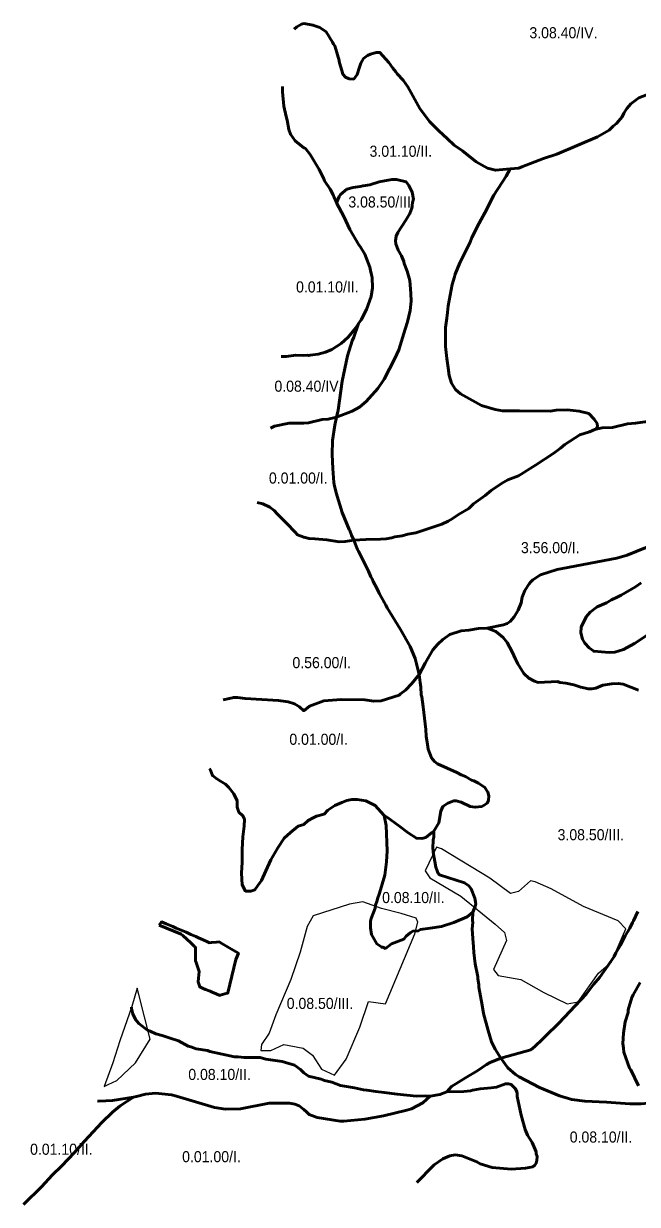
# Model space of a CAD drawing. Extents: x -555506 to -553028, y -1186750 to -1182668.
# Drawn here: x -555506 to -554397, y -1186706 to -1184575 of the extents above; entities that cross this region are included whole.
import ezdxf
from ezdxf.enums import TextEntityAlignment as Align

# ---------------------------------------------------------------- set-up
doc = ezdxf.new("R2010")
doc.units = 0
doc.header["$LTSCALE"] = 8
doc.layers.add('21', color=7, linetype='Continuous', lineweight=53)
doc.layers.add('41', color=7, linetype='Continuous', lineweight=25)
doc.layers.add('22', color=7, linetype='Continuous')

msp = doc.modelspace()

# ---------------------------------------------------------------- linework, layer by layer
at = {"layer": '21'}
for points in [[(-555017.062, -1184585.205), (-555012.312, -1184581.125), (-555003.812, -1184576), (-555000, -1184575.126), (-554989.375, -1184576.875), (-554983.437, -1184577.625), (-554971.125, -1184582.375), (-554959.25, -1184590.001), (-554947.812, -1184608.626), (-554946.125, -1184612), (-554944, -1184615.376), (-554940.187, -1184627.25), (-554938.062, -1184635.75), (-554936.812, -1184639.125), (-554935.5, -1184646.001), (-554931.25, -1184659.5), (-554929.125, -1184666.251), (-554924.5, -1184671.75), (-554917.687, -1184674.751), (-554909.625, -1184675.251), (-554903.312, -1184667.125), (-554899.5, -1184653.625), (-554897.75, -1184650.125), (-554896.937, -1184646.751), (-554892.25, -1184638.251), (-554885.062, -1184632.75), (-554879.562, -1184630.251), (-554868.937, -1184627.25), (-554862.562, -1184627.25), (-554846.5, -1184645.126), (-554839.25, -1184655.251), (-554833.312, -1184662.001), (-554831.187, -1184665.5), (-554820.625, -1184677.376), (-554811.687, -1184689.126), (-554790.5, -1184728.251), (-554772.687, -1184751.875), (-554756.187, -1184768.876), (-554740.937, -1184782.5), (-554728.187, -1184794.376), (-554713.375, -1184804.501), (-554688.75, -1184824.875), (-554668, -1184835.875), (-554653.562, -1184839.751), (-554626.875, -1184837.125)], [(-555038.125, -1184688.404), (-555038.125, -1184695.125), (-555038.562, -1184698.501), (-555036, -1184723.875), (-555031.75, -1184742.5), (-555030.062, -1184749.25), (-555026.687, -1184766.25), (-555024.125, -1184774.75), (-555015.687, -1184786.626), (-555000, -1184799.126), (-554997, -1184800.625), (-554988.062, -1184811.25), (-554972.375, -1184838.376), (-554963.5, -1184855.376), (-554962.25, -1184858.75), (-554952.5, -1184874.001), (-554946.937, -1184884.251), (-554944.875, -1184889.251), (-554943.125, -1184892.751), (-554940.625, -1184898.626)], [(-554626.875, -1184837.125), (-554611.625, -1184835.875), (-554606.062, -1184833.375), (-554566.625, -1184818.5), (-554542.5, -1184810.5), (-554469.562, -1184779.501), (-554447.937, -1184767.251), (-554440.75, -1184760.375), (-554435.25, -1184755.375), (-554424.625, -1184743.501), (-554421.625, -1184736.626), (-554416.125, -1184728.251), (-554408.937, -1184719.751), (-554394.5, -1184709.126), (-554378.812, -1184703.125), (-554375, -1184701), (-554364, -1184690.875)], [(-554940.625, -1184898.626), (-554935.937, -1184887.126), (-554933.375, -1184883.75), (-554921.937, -1184874.001), (-554910.937, -1184871.126), (-554898.187, -1184869.375), (-554892.687, -1184867.626), (-554880.812, -1184866), (-554863.437, -1184860.875), (-554840.562, -1184856.251), (-554832.5, -1184856.251), (-554814.687, -1184860.875), (-554810, -1184867.25), (-554804.062, -1184879.126), (-554801.937, -1184892.25), (-554803.25, -1184897.751), (-554804.937, -1184908), (-554808.312, -1184918.125), (-554815.5, -1184930.001), (-554829.937, -1184952), (-554832.937, -1184958.875), (-554834.187, -1184967.376), (-554833.75, -1184972.376), (-554829.125, -1184984.25), (-554823.562, -1184994.501), (-554819.375, -1185004.626), (-554818.5, -1185008), (-554813, -1185021.626), (-554808.312, -1185038.501), (-554806.625, -1185062.25), (-554805.75, -1185075.875), (-554807.875, -1185092.75), (-554812.562, -1185113.126), (-554816.812, -1185126.75), (-554828.25, -1185164.001), (-554835.437, -1185179.25), (-554854.562, -1185216.625), (-554866, -1185233.625), (-554887.187, -1185257.375), (-554899.5, -1185267.5), (-554912.625, -1185274.751), (-554940.625, -1185285.251)], [(-554626.875, -1184837.125), (-554634.5, -1184850.75), (-554656.562, -1184884.625), (-554662.062, -1184894.876), (-554669.25, -1184910.125), (-554683.25, -1184935.5), (-554696.375, -1184961), (-554699.375, -1184969.375), (-554707.812, -1184986.375), (-554718, -1185006.751), (-554726.5, -1185027.125), (-554727.75, -1185032.126), (-554732, -1185045.75), (-554737.125, -1185074.625), (-554738.812, -1185084.75), (-554740.062, -1185096.625), (-554741.75, -1185106.75), (-554743.875, -1185123.751), (-554743.875, -1185157.626), (-554741.312, -1185179.75), (-554739.187, -1185196.625), (-554737.125, -1185210.25), (-554732.875, -1185223.876), (-554726.062, -1185235.75), (-554716.75, -1185243.376), (-554679, -1185264.126), (-554654, -1185271.75), (-554640.875, -1185274.251), (-554610.312, -1185273.875), (-554554.812, -1185274.751), (-554544.187, -1185273.001), (-554524.25, -1185272.126), (-554502.187, -1185274.751), (-554485.25, -1185279), (-554475.5, -1185288.75), (-554470, -1185297.126), (-554469.562, -1185302.251), (-554471.687, -1185306.875)], [(-554940.625, -1184898.626), (-554927.437, -1184923.25), (-554916.875, -1184947), (-554900.312, -1184974.125), (-554897.75, -1184977.501), (-554889.75, -1184991.001), (-554880.375, -1185014.751), (-554879.125, -1185020.75), (-554877.437, -1185028.376), (-554876.562, -1185033.5), (-554875.75, -1185052.125), (-554878.25, -1185067.375), (-554886.75, -1185091.125), (-554896.062, -1185109.75), (-554900.75, -1185116.501)], [(-555040.994, -1185176.151), (-555031.75, -1185175.626), (-555014, -1185173.501), (-555000, -1185174), (-554993.625, -1185173.75), (-554990.625, -1185174.25), (-554988.062, -1185173.375), (-554974.125, -1185171.626), (-554960.937, -1185168.251), (-554949.062, -1185163.25), (-554932.562, -1185152.625), (-554919.812, -1185140.751), (-554905.812, -1185124.125), (-554900.75, -1185116.501)], [(-554900.75, -1185116.501), (-554909.25, -1185140.751), (-554912.625, -1185147.501), (-554920.687, -1185174.626), (-554930.437, -1185220.375), (-554938.062, -1185273.001), (-554940.625, -1185285.251)], [(-554940.625, -1185285.251), (-554955.875, -1185289.126), (-554966.437, -1185289.501), (-554991.062, -1185295.5), (-555000, -1185296.376), (-555026.25, -1185296.376), (-555052.562, -1185301.501), (-555059.967, -1185305.013)], [(-554940.625, -1185285.251), (-554943.562, -1185300.126), (-554948.25, -1185327.251), (-554948.687, -1185352.75), (-554947.375, -1185378.126), (-554945.687, -1185403.625), (-554944.875, -1185407.001), (-554941.437, -1185422.25), (-554930.437, -1185457.376), (-554917.687, -1185488.375), (-554916.437, -1185490.126), (-554913.5, -1185498.5), (-554909.625, -1185507.5)], [(-554246.562, -1185309.875), (-554256.312, -1185301), (-554273.25, -1185293.375), (-554280.062, -1185291.25), (-554313.125, -1185287.001), (-554342.375, -1185289.126), (-554354.687, -1185290.751), (-554375, -1185292.5), (-554400.875, -1185296.376), (-554415.312, -1185297.625), (-554442, -1185304), (-554461.062, -1185304.75), (-554471.687, -1185306.875)], [(-554909.625, -1185507.5), (-554888, -1185506.25), (-554861.312, -1185505.75), (-554851.125, -1185504.875), (-554841, -1185503.25), (-554835.437, -1185501.501), (-554822.312, -1185499.875), (-554812.125, -1185496.875), (-554797.312, -1185493.876), (-554750.687, -1185478.626), (-554739.187, -1185473.125), (-554732, -1185468.875), (-554720.562, -1185461.25), (-554701.5, -1185450.25), (-554693.437, -1185441.75), (-554672.25, -1185426.5), (-554661.187, -1185418), (-554642.562, -1185405.25), (-554631.125, -1185398.501), (-554612, -1185391.251), (-554581.5, -1185372.25), (-554548.437, -1185350.125), (-554536.125, -1185341.626), (-554528.062, -1185334.875), (-554501.375, -1185317.126), (-554484, -1185311.626), (-554474.25, -1185307.376), (-554471.687, -1185306.875)], [(-555083.848, -1185439.632), (-555074.125, -1185442.126), (-555061, -1185448.001), (-555053.375, -1185454), (-555047.062, -1185460.751), (-555041.937, -1185465.876), (-555037.312, -1185471), (-555030.5, -1185477.251), (-555015.25, -1185493.001), (-555011, -1185497.625), (-555000, -1185502.25), (-554990.187, -1185504.501), (-554979.625, -1185504.875), (-554958.437, -1185507), (-554935.937, -1185510.376), (-554924.937, -1185510), (-554909.625, -1185507.5)], [(-554668.812, -1185666.001), (-554639.125, -1185660.5), (-554632.375, -1185658.001), (-554627.312, -1185654.125), (-554620.062, -1185645.625), (-554612.437, -1185633.751), (-554606.937, -1185620.25), (-554605.25, -1185610.001), (-554600.562, -1185598.251), (-554592.937, -1185586.375), (-554589.562, -1185582.876), (-554586.187, -1185579.126), (-554572.187, -1185570.251), (-554542.062, -1185560.501), (-554532.312, -1185558.75), (-554434.375, -1185539.626), (-554415.75, -1185534.626), (-554383.062, -1185521.001), (-554358.875, -1185506.626), (-554332.187, -1185482.876)], [(-554909.625, -1185507.5), (-554902.875, -1185524.375), (-554901.187, -1185527.376), (-554882.937, -1185563.376), (-554878.687, -1185573.625), (-554876.562, -1185577.001), (-554874.437, -1185582.125), (-554868.125, -1185594.001), (-554865.125, -1185600.75), (-554863, -1185604.126), (-554854.937, -1185619.376), (-554851.562, -1185624.5), (-554849, -1185629.625), (-554825.25, -1185668.626), (-554807.5, -1185699.125), (-554798.562, -1185721.126), (-554791.375, -1185750)], [(-554390.687, -1185584.626), (-554400.437, -1185591.376), (-554426.312, -1185606.625), (-554433.937, -1185610.001), (-554444.125, -1185615.126), (-554453, -1185620.626), (-554470, -1185627.876), (-554482.687, -1185637.25), (-554489.937, -1185645.625), (-554498.812, -1185664.376), (-554499.25, -1185674.501), (-554496.25, -1185686.375), (-554492.062, -1185693.126), (-554484.375, -1185701.626), (-554475.937, -1185708.001), (-554448.375, -1185710.126), (-554437.75, -1185709.25), (-554422.062, -1185704.626), (-554402.562, -1185694), (-554374.187, -1185675.375)], [(-554791.375, -1185750), (-554780.75, -1185729.25), (-554766.75, -1185705.5), (-554757.437, -1185695.251), (-554748.937, -1185686.751), (-554736.25, -1185677.5), (-554715.5, -1185671.125), (-554701.5, -1185669.875), (-554684.125, -1185666.875), (-554668.812, -1185666.001)], [(-554395.375, -1185778.376), (-554422.937, -1185767.375), (-554432.25, -1185766.126), (-554443.25, -1185766.5), (-554459.812, -1185769), (-554472.562, -1185774.626), (-554479.312, -1185775.875), (-554485.687, -1185775.875), (-554499.687, -1185772.875), (-554511.937, -1185768.625), (-554526.812, -1185765.25), (-554537.375, -1185764.001), (-554541.625, -1185762.75), (-554576.437, -1185764.001), (-554583.187, -1185761.876), (-554593.375, -1185756.375), (-554602.25, -1185747.875), (-554613.312, -1185730.875), (-554617.562, -1185722.376), (-554623.5, -1185708.876), (-554632.375, -1185691.875), (-554639.562, -1185683.375), (-554652.75, -1185672), (-554668.812, -1185666.001)], [(-555145.556, -1185795.729), (-555134.312, -1185793.001), (-555126.25, -1185791.251), (-555119.5, -1185791.251), (-555105.937, -1185793.001), (-555045.75, -1185796.751), (-555028.375, -1185799.375), (-555016.5, -1185802.75), (-555007.625, -1185808.251), (-555000, -1185815.25), (-554989.812, -1185807.25), (-554963.937, -1185797.5), (-554932.562, -1185794.876), (-554889.75, -1185795.375), (-554873.625, -1185798.25), (-554860.062, -1185797.5), (-554827.812, -1185786.876), (-554824.875, -1185784.751), (-554815.937, -1185778), (-554804.5, -1185766.126), (-554791.375, -1185750)], [(-554791.375, -1185750), (-554789.687, -1185764.375), (-554788.375, -1185772.875), (-554787.562, -1185786.5), (-554786.687, -1185789.876), (-554784.125, -1185808.501), (-554779.5, -1185849.125), (-554778.625, -1185861.001), (-554776.5, -1185876.375), (-554775.25, -1185884.751), (-554768.875, -1185900.126), (-554763.812, -1185906.876), (-554758.312, -1185911.126), (-554723.125, -1185926.75), (-554715.875, -1185931), (-554707.812, -1185934.001), (-554696.812, -1185940.376), (-554692.562, -1185941.625), (-554690.062, -1185943.25), (-554684.125, -1185945.875), (-554672.625, -1185953.501), (-554667.125, -1185962.001), (-554665.437, -1185968.75), (-554666.312, -1185977.25), (-554668.812, -1185982.375), (-554673.937, -1185985.751), (-554678.187, -1185987.876), (-554690.062, -1185989.5), (-554699.375, -1185988.25), (-554715.5, -1185980.25), (-554724.812, -1185978.125), (-554729.062, -1185978.125), (-554739.625, -1185981.875), (-554748.562, -1185988.25), (-554752.375, -1185996.75), (-554755.75, -1186017.5), (-554765.062, -1186032.75)], [(-554854.937, -1186004.376), (-554860.875, -1185997.626), (-554871.062, -1185986.125), (-554887.625, -1185978.125), (-554903.312, -1185975.5), (-554913.062, -1185975.5), (-554921.937, -1185977.25), (-554931.25, -1185980.626), (-554943.562, -1185986.125), (-554956.687, -1185995.001), (-554963.062, -1186001.875), (-554976.625, -1186005.626), (-554983, -1186008.626), (-554991.875, -1186013.25), (-555000, -1186020.626), (-555009.75, -1186023.501), (-555023.75, -1186035.001), (-555035.187, -1186045.5), (-555046.625, -1186062.875), (-555059.312, -1186084.501), (-555068.25, -1186104.001), (-555076.25, -1186121.376), (-555083.062, -1186130.75), (-555088.562, -1186138.376), (-555095.75, -1186140.875), (-555105.062, -1186140.875), (-555111.437, -1186129.376), (-555112.687, -1186108.625), (-555111, -1186088.75), (-555111, -1186076.001), (-555111, -1186065.876), (-555110.187, -1186042.625), (-555107.625, -1186023.501), (-555107.187, -1186011.251), (-555110.187, -1186004.876), (-555117.375, -1185998.125), (-555120.375, -1185989.126), (-555120.375, -1185977.751), (-555126.25, -1185965), (-555135.187, -1185954.001), (-555141.5, -1185947.626), (-555150.437, -1185942.501), (-555157.187, -1185938.375), (-555164.812, -1185932.376), (-555168.625, -1185922.251), (-555169.98, -1185919.441)], [(-554694.25, -1186178.626), (-554704.875, -1186187.5), (-554728.625, -1186197.251), (-554751.062, -1186204.501), (-554771.875, -1186207.5), (-554788.812, -1186210.376), (-554793.5, -1186212.501), (-554802.812, -1186213.375), (-554807.875, -1186215.876), (-554814.687, -1186221.875), (-554819.375, -1186227.75), (-554841.375, -1186236.25), (-554852.437, -1186244.376), (-554857.062, -1186242.251), (-554859.187, -1186242.251), (-554867.687, -1186235.876), (-554877.437, -1186218.876), (-554879.125, -1186207), (-554879.562, -1186195.126), (-554877.875, -1186190.126), (-554871.062, -1186171.376), (-554870.25, -1186166.376), (-554867.25, -1186157.876), (-554866.812, -1186154.5), (-554863, -1186144.251), (-554853.687, -1186112.001), (-554850.312, -1186088.251), (-554849, -1186068.001), (-554851.125, -1186022.125), (-554854.937, -1186004.376)], [(-554765.062, -1186032.75), (-554769.312, -1186035.751), (-554779.5, -1186044.25), (-554786.687, -1186045.876), (-554796.437, -1186045.5), (-554811.312, -1186035.751), (-554828.687, -1186022.125), (-554848.625, -1186007.75), (-554854.937, -1186004.376)], [(-554694.25, -1186178.626), (-554690.437, -1186168.875), (-554689.187, -1186163.751), (-554690.875, -1186153.626), (-554697.687, -1186136.625), (-554701.5, -1186131.501), (-554709.562, -1186125.626), (-554754.875, -1186111.251), (-554757.437, -1186107.751), (-554759.125, -1186104.375), (-554761.25, -1186097.626), (-554766.375, -1186070.5), (-554766.375, -1186067.125), (-554766.75, -1186063.751), (-554766.375, -1186048.5), (-554765.062, -1186043.375), (-554765.062, -1186032.75)], [(-554643.812, -1186442.376), (-554654.437, -1186426.25), (-554658.25, -1186417.75), (-554660.75, -1186412.625), (-554666.687, -1186392.251), (-554675.187, -1186361.75), (-554677.75, -1186346.501), (-554683.687, -1186314.251), (-554683.687, -1186309.25), (-554685.375, -1186299.001), (-554685.375, -1186295.626), (-554686.187, -1186292.25), (-554690.437, -1186271.876), (-554693, -1186251.5), (-554693.437, -1186241.375), (-554694.687, -1186226.125), (-554696, -1186209.125), (-554694.687, -1186197.251), (-554695.125, -1186193.875), (-554694.25, -1186178.626)], [(-554643.812, -1186442.376), (-554590, -1186427.125), (-554582.375, -1186421.5), (-554568.75, -1186408.001), (-554563.25, -1186402.875), (-554539.125, -1186379.125), (-554489.937, -1186326.625), (-554476.375, -1186309.625), (-554464.875, -1186296), (-554457.687, -1186285.875), (-554450.5, -1186275.75), (-554439.062, -1186258.751), (-554436.062, -1186252), (-554428, -1186238.375), (-554419.562, -1186221.501), (-554410.625, -1186207.876), (-554406, -1186197.751), (-554404.25, -1186194.25), (-554396.187, -1186177.375)], [(-554395.375, -1186492.375), (-554409.375, -1186463.501), (-554411.5, -1186460.125), (-554421.625, -1186431.251), (-554422.5, -1186424.501), (-554423.75, -1186416.001), (-554422.062, -1186397.376), (-554419.125, -1186377), (-554414, -1186360.126), (-554413.625, -1186355.001), (-554407.25, -1186333), (-554404.687, -1186327.876), (-554392.375, -1186305.751)], [(-554771.437, -1186511), (-554779.5, -1186510.126), (-554796.437, -1186510.626), (-554831.187, -1186507.25), (-554854.562, -1186504.251), (-554869.812, -1186502.5), (-554885.937, -1186500.001), (-554891.875, -1186499.626), (-554908.375, -1186495.751), (-554933.812, -1186491.875), (-554949.062, -1186485.626), (-554962.625, -1186482.626), (-554968.187, -1186480.501), (-554991.062, -1186475), (-555000, -1186468.751), (-555005.937, -1186462.5), (-555016.5, -1186454.876), (-555039, -1186448.501), (-555068.625, -1186443.875), (-555078.375, -1186440.875), (-555107.625, -1186441.25), (-555118.25, -1186440.001), (-555125, -1186440.001), (-555147.437, -1186435.001), (-555169.5, -1186430.25), (-555173.75, -1186428.625), (-555194.062, -1186425.25), (-555203.812, -1186421.876), (-555208.5, -1186420.501), (-555226.25, -1186411.251), (-555241.125, -1186406.5), (-555255.5, -1186401.5), (-555267.375, -1186398.126), (-555277.562, -1186393.376), (-555282.187, -1186391.751), (-555286.875, -1186387.875), (-555297.875, -1186379.501), (-555303.812, -1186372.626), (-555308.5, -1186362.501), (-555311, -1186352.376), (-555311.091, -1186350.268)], [(-554741.75, -1186503), (-554733.25, -1186493.625), (-554707.812, -1186477.5), (-554685.375, -1186464.751), (-554669.687, -1186453.75), (-554663.312, -1186450.376), (-554643.812, -1186442.376)], [(-554643.812, -1186442.376), (-554631.5, -1186459.751), (-554617.562, -1186471.625), (-554610.75, -1186475.875), (-554573.875, -1186495.376), (-554538.25, -1186510.126), (-554515.75, -1186517.001), (-554492.062, -1186519.876), (-554453, -1186521.625), (-554411.062, -1186524.625), (-554390.25, -1186524.625), (-554377.562, -1186523.75), (-554366.937, -1186524.625)], [(-554741.75, -1186503), (-554710.812, -1186502.5), (-554698.5, -1186501.251), (-554694.687, -1186500.001), (-554681.562, -1186497.501), (-554661.187, -1186495.751), (-554651.875, -1186494.5), (-554635.312, -1186488.501), (-554629.812, -1186488.501), (-554625.187, -1186489.876), (-554617.562, -1186497.876), (-554615, -1186503), (-554614.125, -1186506.376), (-554614.125, -1186511.5), (-554606.937, -1186545.375), (-554600.125, -1186570.75), (-554595.5, -1186581.001), (-554587.437, -1186594.501), (-554580.25, -1186611.5), (-554580.25, -1186614.875), (-554578.5, -1186620), (-554578.937, -1186626.751), (-554580.25, -1186631.876), (-554582.75, -1186635.251), (-554586.187, -1186638.251), (-554599.312, -1186641.126), (-554625.562, -1186642.501), (-554659.5, -1186639.5), (-554681.125, -1186632.75), (-554687.062, -1186629.25), (-554714.625, -1186618.751), (-554726.5, -1186617), (-554736.25, -1186618.751), (-554748.937, -1186624.25), (-554764.25, -1186634.875), (-554774.375, -1186645), (-554787.125, -1186658.501), (-554795.617, -1186666.413)], [(-555307.625, -1186512.875), (-555331.375, -1186528.126), (-555345.375, -1186540), (-555364.812, -1186558.626), (-555395.75, -1186592.126), (-555405.5, -1186602.751), (-555414.437, -1186612.876), (-555436.875, -1186636.626), (-555454.25, -1186653.626), (-555473.312, -1186674.001), (-555506.016, -1186706.203)], [(-555372.298, -1186519.611), (-555369.5, -1186519.75), (-555345.375, -1186518.876), (-555307.625, -1186512.875)], [(-555307.625, -1186512.875), (-555302.125, -1186511.25), (-555286, -1186507.376), (-555267.812, -1186505.75), (-555239, -1186508.625), (-555229.687, -1186510.75), (-555161, -1186531.626), (-555141.125, -1186534.5), (-555114, -1186533.625), (-555062.687, -1186523.5), (-555025.437, -1186523.5), (-555016.125, -1186525.251), (-555008.062, -1186528.625), (-555000, -1186534.75), (-554994.875, -1186539.376), (-554990.187, -1186544.126), (-554975.812, -1186549.125), (-554934.25, -1186556), (-554927.437, -1186556), (-554889.312, -1186552.126), (-554855.812, -1186546.25), (-554813.812, -1186536), (-554805.375, -1186533.501), (-554785, -1186522.876), (-554771.437, -1186511)], [(-554771.437, -1186511), (-554754.062, -1186508.001), (-554741.75, -1186503)]]:
    msp.add_lwpolyline(points, dxfattribs=at)
msp.add_lwpolyline([(-555261.28, -1186202.32), (-555256.91, -1186196.5), (-555248.77, -1186199.76), (-555242.74, -1186202.33), (-555236.71, -1186204.91), (-555230.2, -1186207.64), (-555212.56, -1186215.1), (-555203.72, -1186218.85), (-555194.89, -1186222.61), (-555190.05, -1186224.85), (-555185.99, -1186226.72), (-555175.06, -1186231.77), (-555170.16, -1186234.03), (-555166.5, -1186233.72), (-555157.32, -1186232.94), (-555153.01, -1186232.57), (-555147.8, -1186235.58), (-555137.45, -1186241.58), (-555127.54, -1186247.31), (-555121.87, -1186250.59), (-555117.88, -1186252.9), (-555122.79, -1186264.03), (-555136.85, -1186324.41), (-555138.36, -1186325.06), (-555142.52, -1186326.28), (-555150.68, -1186328.68), (-555151.71, -1186328.98), (-555157.95, -1186326.36), (-555165.36, -1186323.24), (-555169.27, -1186321.6), (-555177.22, -1186318.25), (-555181.71, -1186316.36), (-555186.26, -1186314.45), (-555187.71, -1186313.84), (-555190.76, -1186304.59), (-555190.1, -1186297.86), (-555188.93, -1186285.88), (-555194.7, -1186268.11), (-555195.22, -1186267.63), (-555195.64, -1186245.84), (-555195.72, -1186241.89), (-555197.18, -1186240.55), (-555204.2, -1186234.11), (-555218.31, -1186221.15), (-555221.4, -1186218.64)], close=True, dxfattribs=at)
at = {"layer": '41'}
for points in [[(-554760.17, -1186061.511), (-554780.396, -1186104.412), (-554772.306, -1186116.554), (-554716.481, -1186149.742), (-554654.183, -1186200.738), (-554637.192, -1186215.308), (-554633.956, -1186229.879), (-554657.419, -1186282.494), (-554648.519, -1186293.017), (-554608.066, -1186300.302)], [(-554608.066, -1186300.302), (-554565.995, -1186323.776), (-554523.924, -1186344.013), (-554504.506, -1186340.775), (-554467.289, -1186288.97), (-554443.827, -1186268.733), (-554417.937, -1186208.833), (-554431.691, -1186194.262), (-554494.798, -1186168.36), (-554553.05, -1186136.791), (-554582.176, -1186123.839), (-554590.267, -1186122.22), (-554612.112, -1186141.647), (-554626.675, -1186144.885), (-554663.891, -1186117.364), (-554751.27, -1186064.748), (-554760.17, -1186061.511)], [(-555059.12, -1186428.197), (-555035.657, -1186417.674), (-555000.868, -1186424.15), (-554983.878, -1186437.101), (-554967.696, -1186462.195), (-554944.233, -1186472.718), (-554923.198, -1186444.386), (-554898.926, -1186386.105), (-554882.745, -1186339.966), (-554852, -1186344.013), (-554799.411, -1186217.737), (-554793.748, -1186196.691), (-554796.984, -1186189.406), (-554823.683, -1186181.311), (-554859.282, -1186172.407), (-554893.263, -1186160.265), (-554917.534, -1186164.312), (-554983.068, -1186185.358), (-554993.586, -1186204.785), (-555006.531, -1186250.925), (-555023.522, -1186300.302), (-555050.221, -1186364.25), (-555062.357, -1186397.438), (-555076.111, -1186417.674)], [(-555360.544, -1186493.27), (-555353.313, -1186489.756), (-555353.231, -1186489.716), (-555337.86, -1186482.431), (-555303.88, -1186450.862), (-555277.182, -1186407.961), (-555297.741, -1186327.672), (-555300.744, -1186315.945)], [(-555300.744, -1186315.945), (-555310.66, -1186348.84), (-555332.46, -1186411.11), (-555344.77, -1186450.74), (-555360.544, -1186493.27)], [(-555076.111, -1186417.674), (-555077.729, -1186428.197), (-555059.12, -1186428.197)]]:
    msp.add_lwpolyline(points, dxfattribs=at)

# ---------------------------------------------------------------- texts
at = {"layer": '22', "width": 0.95}
for s, p in [('3.08.40/IV.', (-554530.829, -1184601.564)), ('3.01.10/II.', (-554824.56, -1184815.454)), ('3.08.50/III.', (-554859.303, -1184907.01)), ('0.01.10/II.', (-554957.313, -1185060.316)), ('0.08.40/IV.', (-554991.427, -1185239.511)), ('0.01.00/I.', (-555009.87, -1185405.268)), ('3.56.00/I.', (-554554.579, -1185530.906)), ('0.56.00/I.', (-554967.397, -1185738.432)), ('0.01.00/I.', (-554972.98, -1185876.775)), ('3.08.50/III.', (-554481.347, -1186048.976)), ('0.08.10/II.', (-554801.827, -1186162.374)), ('0.08.50/III.', (-554970.614, -1186353.508)), ('0.08.10/II.', (-555152.002, -1186481.703)), ('0.08.10/II.', (-554462.956, -1186594.633)), ('0.01.10/II.', (-555437.765, -1186616.655)), ('0.01.00/I.', (-555166.618, -1186630.066))]:
    msp.add_text(s, height=20, dxfattribs=at).set_placement(p, align=Align.CENTER)

doc.saveas('drawing.dxf')
